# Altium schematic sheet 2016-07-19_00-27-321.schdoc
size 267 x 118 mm; SheetNumber: 1; SheetTotal: 1
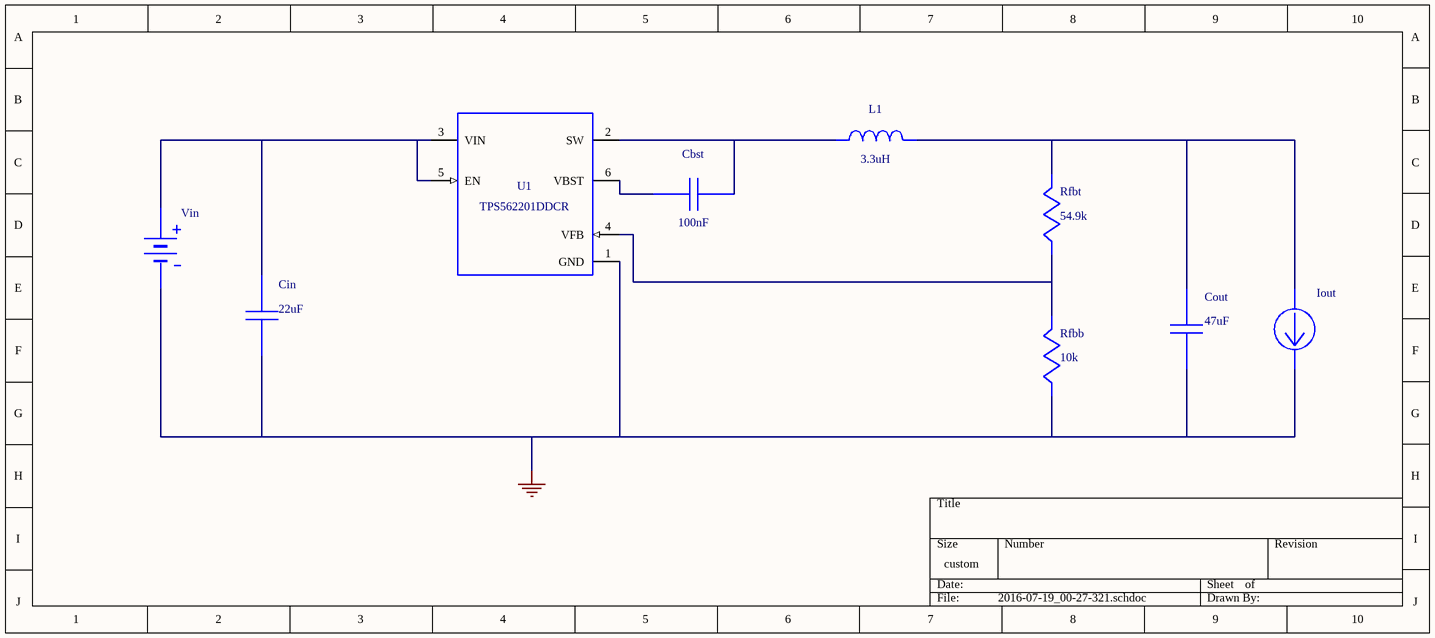
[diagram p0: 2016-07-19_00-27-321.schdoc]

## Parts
Cbst  value 100nF  (hidden comment: 08053C104KAT2A)
Cin  value 22uF  (hidden comment: GRM32ER61E226KE15L)
Cout  value 47uF  (hidden comment: C3216X5R1E476M160AC)
Iout  WB_CURRENT_LOAD  (value not drawn)
L1  value 3.3uH  (hidden comment: SRR6038-3R3Y)
Rfbb  value 10k  (hidden comment: CRCW040210K0FKED)
Rfbt  value 54.9k  (hidden comment: CRCW040254K9FKED)
U1  TPS562201DDCR
Vin  WB_BATTERY  (value not drawn)

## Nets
0: Cin.2 Cout.2 Iout.2(-) Rfbb.2 U1.1(GND) Vin.2(-)
NetCbst_1: Cbst.1 L1.1 U1.2(SW)
NetCbst_2: Cbst.2 U1.6(VBST)
NetCin_1: Cin.1 U1.3(VIN) U1.5(EN) Vin.1(+)
NetCout_1: Cout.1 Iout.1(+) L1.2 Rfbt.1
NetRfbb_1: Rfbb.1 Rfbt.2 U1.4(VFB)

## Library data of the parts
Cbst = 08053C104KAT2A: Manufacturer Name: AVX
Cin = GRM32ER61E226KE15L: GRM32ER61E226KE1; Manufacturer Name: MuRata
Cout = C3216X5R1E476M160AC: C3216X5R1E476M16; Manufacturer Name: TDK
L1 = SRR6038-3R3Y: Manufacturer Name: Bourns
Rfbb = CRCW040210K0FKED: Manufacturer Name: Vishay-Dale
Rfbt = CRCW040254K9FKED: Manufacturer Name: Vishay-Dale
U1 = TPS562201DDCR: Manufacturer Name: Texas Instruments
